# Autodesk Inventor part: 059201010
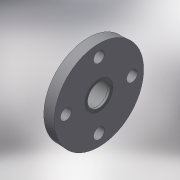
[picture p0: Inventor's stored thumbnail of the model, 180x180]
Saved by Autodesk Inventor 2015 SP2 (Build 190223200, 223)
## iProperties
Created: 2017-10
Part Number: 059201010
Material: Generic
Description: PLASSON THR. FIXED FLANGE PVC 1"
Document SubType Name: Modeling
Designer: KIM
Density: 1 g/cm^3
Appearance: Default
Author: KIM
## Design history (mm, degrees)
derived "059201.ipt"
feature "Solid1::059201.ipt"
tag "TaggingFeature1"
body "Solid1"
other parameters: "d0" = 23, "d2" = 115, "d3" = 113.85, "d14" = 14, "d15" = 42.5, "d16" = 23, "d17" = 0, "d19" = 360 deg, "d22" = 30.291, "d23" = 28.77645, "d25" = 0.30291, "d26" = 0.575, "d27" = 0.575, "d28" = 0.575, "d29" = 0.575, "d30" = 0.575, "d31" = 0.575, "d32" = 0.23, "d33" = 0, "d34" = 14, "d35" = 36.3492, "E_" = 115, "H_" = 23, "Dp_" = 85, "S_" = 14, "G_" = 30.291, "H_1" = 14
